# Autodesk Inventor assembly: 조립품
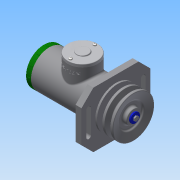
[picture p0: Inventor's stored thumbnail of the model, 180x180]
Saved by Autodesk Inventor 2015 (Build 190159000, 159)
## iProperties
Created: 2017-10
Part Number: 조립품
Document SubType Name: Assembly
Designer: user
Author: user
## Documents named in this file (19)
- C:\Users\user\Desktop\471007V1008\조립품.iam
- C:\Users\user\Desktop\471007V1008\본체.ipt
- C:\Users\user\Desktop\471007V1008\사이드 커버.ipt
- 사이드 커버.ipt
- C:\Users\user\Desktop\471007V1008\축.ipt
- C:\Users\user\Desktop\471007V1008\멈춤링 15 x 1.ipt
- C:\Users\user\Desktop\471007V1008\베어링 15 x 35 x 11.ipt
- C:\Users\user\Desktop\471007V1008\부시1.ipt
- C:\Users\user\Desktop\471007V1008\멈춤링 35x1.6.ipt
- C:\Users\user\Desktop\471007V1008\부시2.ipt
- C:\Users\user\Desktop\471007V1008\와셔 10x21.ipt
- C:\Users\user\Desktop\471007V1008\너트 M10.ipt
- C:\Users\user\Desktop\471007V1008\오일 실 15 25 7.ipt
- C:\Users\user\Desktop\471007V1008\V-벨트풀리.ipt
- C:\Users\user\Desktop\471007V1008\와셔 4x16.ipt
- C:\Users\user\Desktop\471007V1008\볼트 M4 x 10.ipt
- C:\Users\user\Desktop\471007V1008\키 4 x 4 x 18.ipt
- C:\Users\user\Desktop\471007V1008\탑 커버.ipt
- C:\Users\user\Desktop\471007V1008\십자볼트 M3 x 10.ipt
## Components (2 placed, 2 different names)
1. V-벨트풀리:1
2. ISO 4017 M4 x 10:1
